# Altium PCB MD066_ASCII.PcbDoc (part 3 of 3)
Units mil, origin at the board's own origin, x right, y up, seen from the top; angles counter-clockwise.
Board outline 4255 x 2850 mil, 4 copper layers (Top Layer, Ground, Power, Bottom Layer), stack 61.6 mil thick; 158 components, 78 nets, 405 pads, 639 vias.
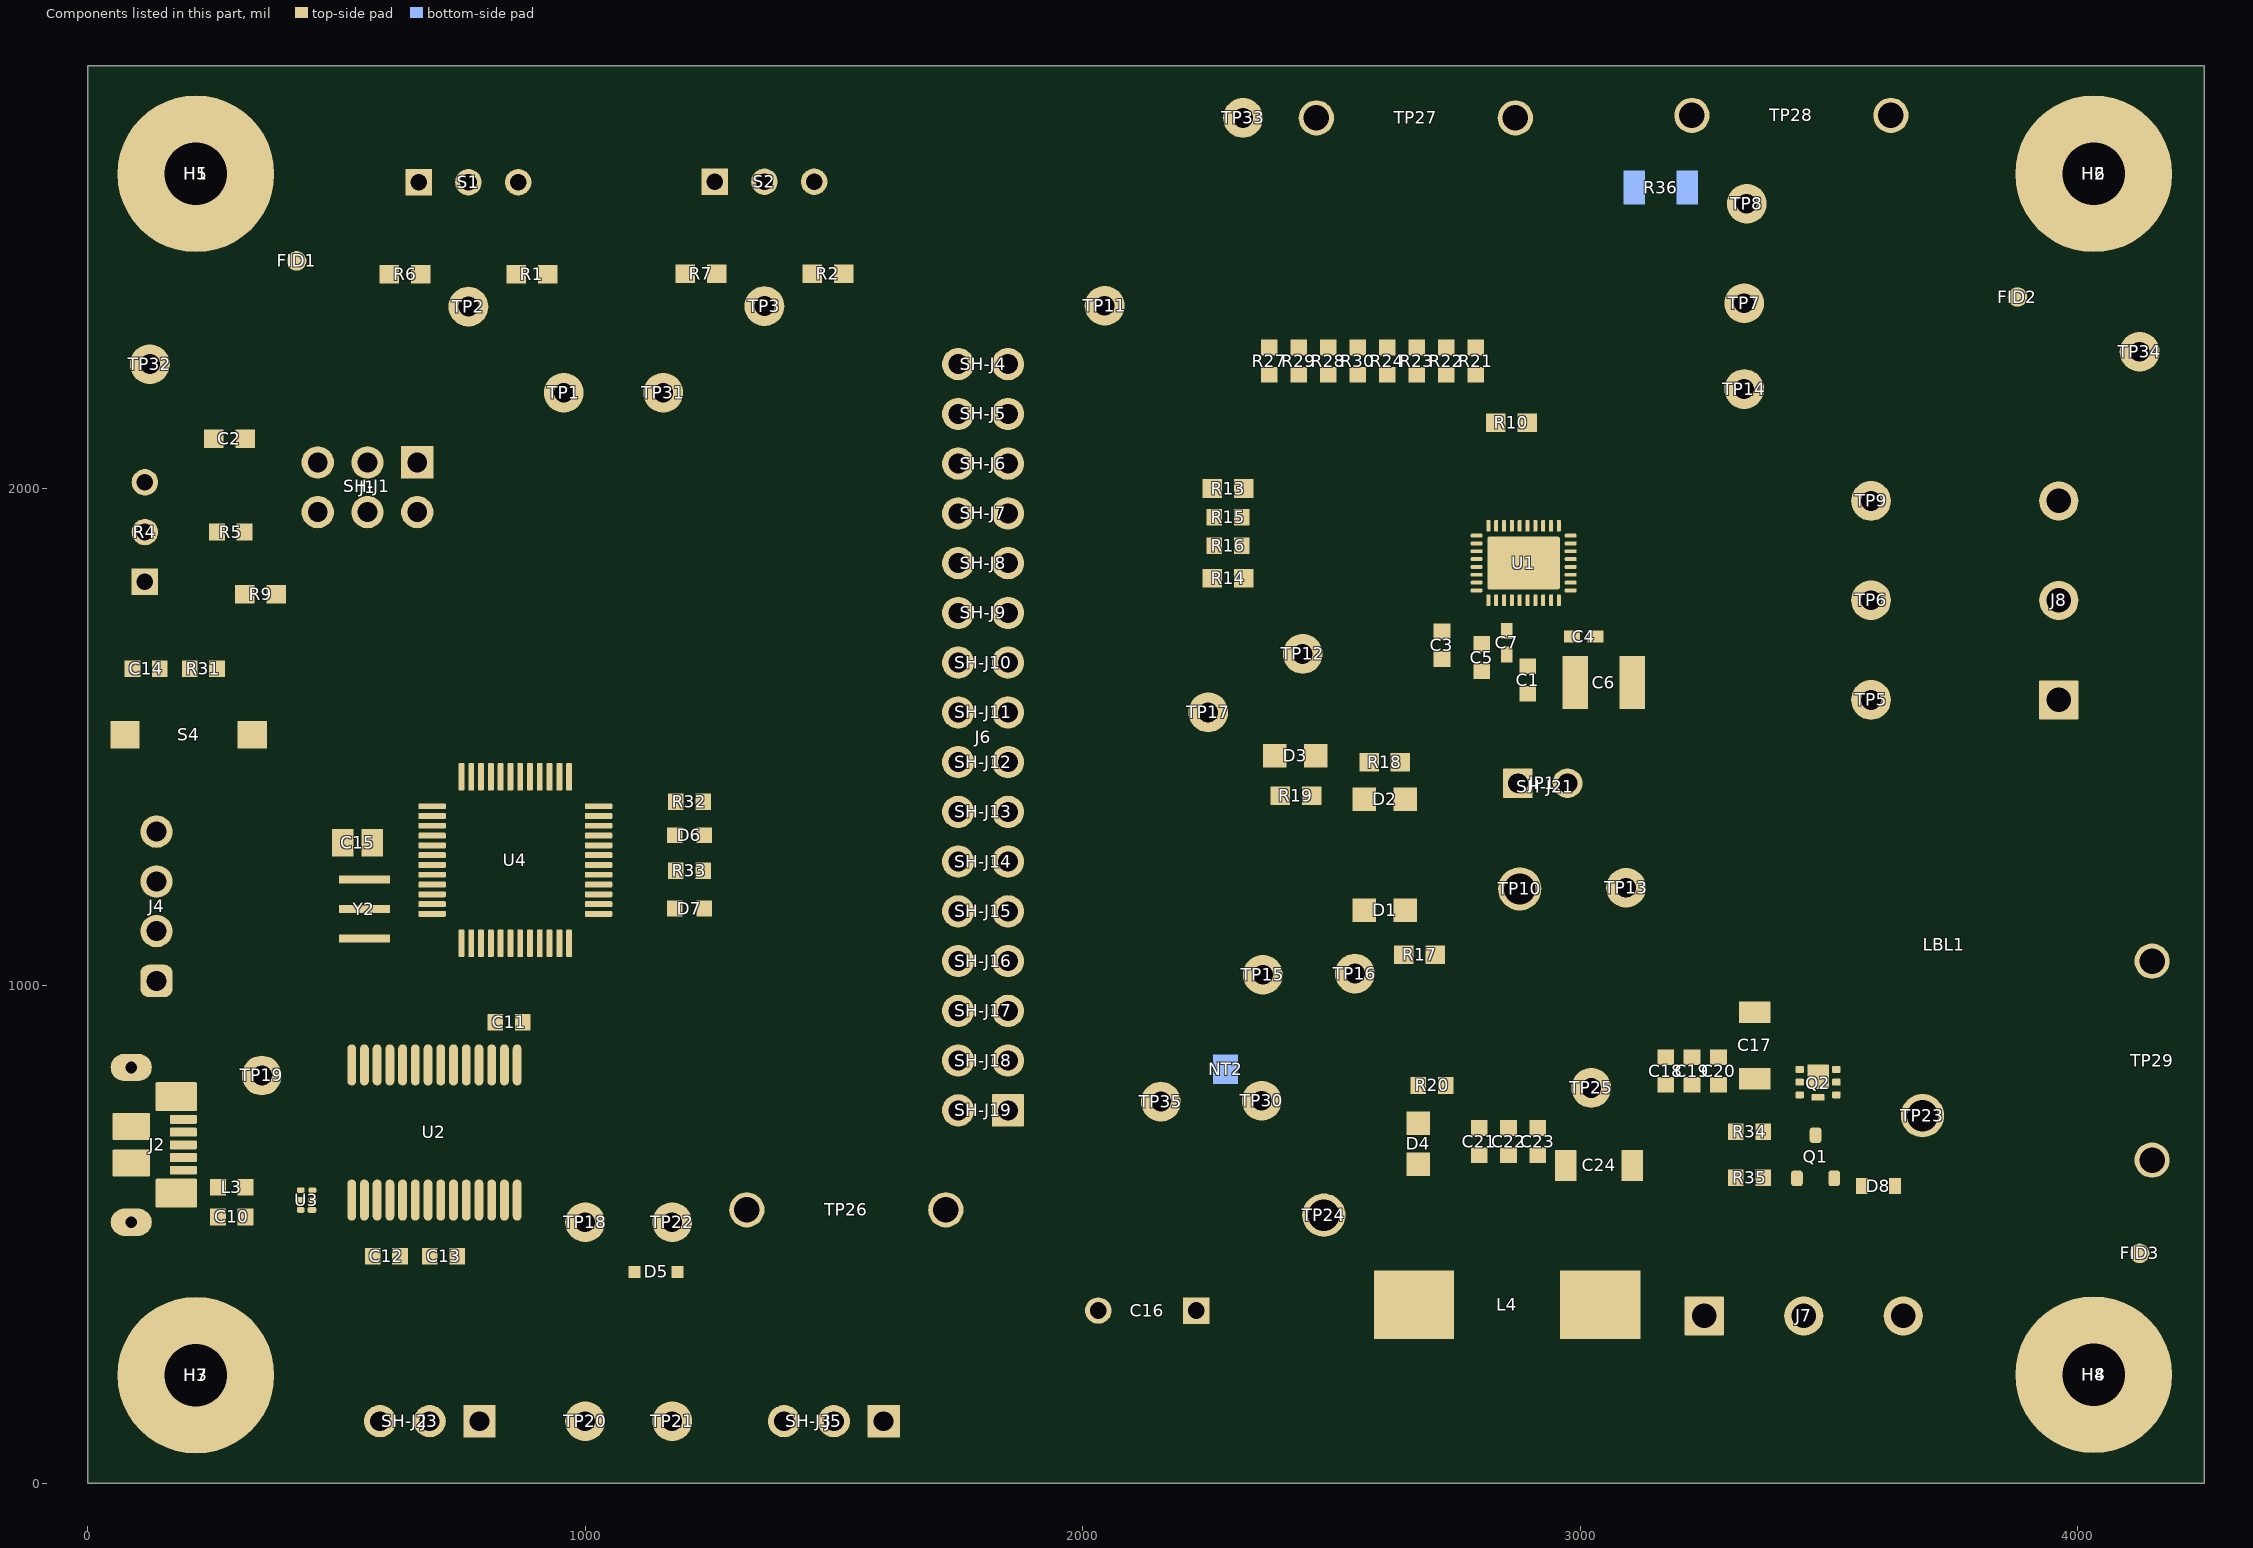
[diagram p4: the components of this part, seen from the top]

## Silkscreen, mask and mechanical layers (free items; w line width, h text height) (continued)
Drill Drawing:
  circle w10: c5363.72,3507.55 r16.58
  circle w10: c5363.72,3507.55 r27.63
  circle w10: c5363.72,3383.23 r27.63
  lines w10: 5336.09,3010.27 5363.72,2982.64 5391.34,3010.27 5363.72,3037.9 5336.09,3010.27 ; 5336.09,3120.78 5349.9,3120.78 5349.9,3106.96 5377.53,3106.96 5377.53,3120.78 5391.34,3120.78 5391.34,3148.4 5377.53,3148.4 5377.53,3162.22 5349.9,3162.22 5349.9,3148.4 5336.09,3148.4 5336.09,3120.78 ; 5336.09,3231.28 5391.34,3231.28 5391.34,3286.54 5336.09,3286.54 5336.09,3231.28 ; 5336.09,3604.24 5336.09,3618.06 5349.9,3631.87 5336.09,3645.68 5336.09,3659.5 5349.9,3659.5 5363.72,3645.68 5377.53,3659.5 5391.34,3659.5 5391.34,3645.68 5377.53,3631.87 5391.34,3618.06 5391.34,3604.24 5377.53,3604.24 5363.72,3618.06 5349.9,3604.24 5336.09,3604.24 ; 5336.09,3742.38 5349.9,3742.38 5363.72,3728.56 5377.53,3742.38 5391.34,3742.38 5377.53,3756.19 5391.34,3770 5377.53,3770 5363.72,3783.82 5349.9,3770 5336.09,3770 5349.9,3756.19 5336.09,3742.38 ; 5336.09,3908.14 5391.34,3908.14 5363.72,3852.88 5336.09,3908.14 ; 5336.09,3977.2 5363.72,3991.02 5391.34,3977.2 5377.53,4004.83 5391.34,4032.46 5363.72,4018.64 5336.09,4032.46 5349.9,4004.83 5336.09,3977.2 ; 5336.09,4101.52 5391.34,4101.52 5391.34,4156.78 5336.09,4156.78 5336.09,4101.52 ; 5347.14,4112.57 5380.29,4112.57 5380.29,4145.73 5347.14,4145.73 5347.14,4112.57
  lines w12: 5286,2945.35 8517.49,2945.35 ; 5286,4188.55 8517.49,4188.55 ; 5623.86,2821.03 5623.86,4312.87 ; 5955.86,2821.03 5955.86,4312.87 ; 6592.43,2821.03 6592.43,4312.87 ; 6851.57,2821.03 6851.57,4312.87 ; 7226.72,2821.03 7226.72,4312.87 ; 7951.05,2821.03 7951.05,4312.87 ; 5286,2821.03 8517.49,2821.03 8517.49,4312.87 5286,4312.87 5286,2821.03
  text "Symbol" at 5360.59,4225.84 h72
  text "Quantity" at 5661.16,4225.84 h72
  text "Finished Hole Size" at 5993.16,4225.84 h72
  text "Plated" at 6629.72,4225.84 h72
  text "Hole Type" at 6888.86,4225.84 h72
  text "Drill Layer Pair" at 7264.02,4225.84 h72
  text "Hole Tolerance" at 7988.35,4225.84 h72
  text "8" at 5661.16,4101.52 h60
  text "7.87mil (0.200mm)" at 5993.16,4101.52 h60
  text "PTH" at 6629.72,4101.52 h60
  text "Round" at 6888.86,4101.52 h60
  text "Top Layer - Bottom Layer" at 7264.02,4101.52 h60
  text "631" at 5661.16,3977.2 h60
  text "10.00mil (0.254mm)" at 5993.16,3977.2 h60
  text "PTH" at 6629.72,3977.2 h60
  text "Round" at 6888.86,3977.2 h60
  text "Top Layer - Bottom Layer" at 7264.02,3977.2 h60
  text "11" at 5661.16,3852.88 h60
  text "33.47mil (0.850mm)" at 5993.16,3852.88 h60
  text "PTH" at 6629.72,3852.88 h60
  text "Round" at 6888.86,3852.88 h60
  text "Top Layer - Bottom Layer" at 7264.02,3852.88 h60
  text "75" at 5661.16,3728.56 h60
  text "40.00mil (1.016mm)" at 5993.16,3728.56 h60
  text "PTH" at 6629.72,3728.56 h60
  text "Round" at 6888.86,3728.56 h60
  text "Top Layer - Bottom Layer" at 7264.02,3728.56 h60
  text "2" at 5661.16,3604.24 h60
  text "40.16mil (1.020mm)" at 5993.16,3604.24 h60
  text "PTH" at 6629.72,3604.24 h60
  text "Round" at 6888.86,3604.24 h60
  text "Top Layer - Bottom Layer" at 7264.02,3604.24 h60
  text "6" at 5661.16,3479.92 h60
  text "49.21mil (1.250mm)" at 5993.16,3479.92 h60
  text "PTH" at 6629.72,3479.92 h60
  text "Round" at 6888.86,3479.92 h60
  text "Top Layer - Bottom Layer" at 7264.02,3479.92 h60
  text "8" at 5661.16,3355.6 h60
  text "51.18mil (1.300mm)" at 5993.16,3355.6 h60
  text "PTH" at 6629.72,3355.6 h60
  text "Round" at 6888.86,3355.6 h60
  text "Top Layer - Bottom Layer" at 7264.02,3355.6 h60
  text "3" at 5661.16,3231.28 h60
  text "63.00mil (1.600mm)" at 5993.16,3231.28 h60
  text "PTH" at 6629.72,3231.28 h60
  text "Round" at 6888.86,3231.28 h60
  text "Top Layer - Bottom Layer" at 7264.02,3231.28 h60
  text "4" at 5661.16,3106.96 h60
  text "125.98mil (3.200mm)" at 5993.16,3106.96 h60
  text "PTH" at 6629.72,3106.96 h60
  text "Round" at 6888.86,3106.96 h60
  text "Top Layer - Bottom Layer" at 7264.02,3106.96 h60
  text "2" at 5661.16,2982.64 h60
  text "23.62mil (0.600mm)" at 5993.16,2982.64 h60
  text "PTH" at 6629.72,2982.64 h60
  text "Slot" at 6888.86,2982.64 h60
  text "Top Layer - Bottom Layer" at 7264.02,2982.64 h60
  text "750 Total" at 5661.16,2858.32 h60
  text "Slot definitions :" at 5360.59,2771.3 h60
  text "Routed Path Length" at 5811.31,2771.3 h60
  text "= Calculated from tool start centre position to tool end centre position." at 6351.05,2771.3 h60
  text "Hole Length" at 5811.31,2721.57 h60
  text "= Routed Path Length + Tool Size = Slot length as defined in the PCB layout" at 6151.24,2721.57 h60
  text ".Layer_Name" at 577,-858.49 h60
Mechanical 17:
  text ".Layer_Name" at 577,-858.49 h60
Mechanical 18:
  text ".Layer_Name" at 577,-858.49 h60
Mechanical 19:
  text ".Layer_Name" at 577,-858.49 h60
